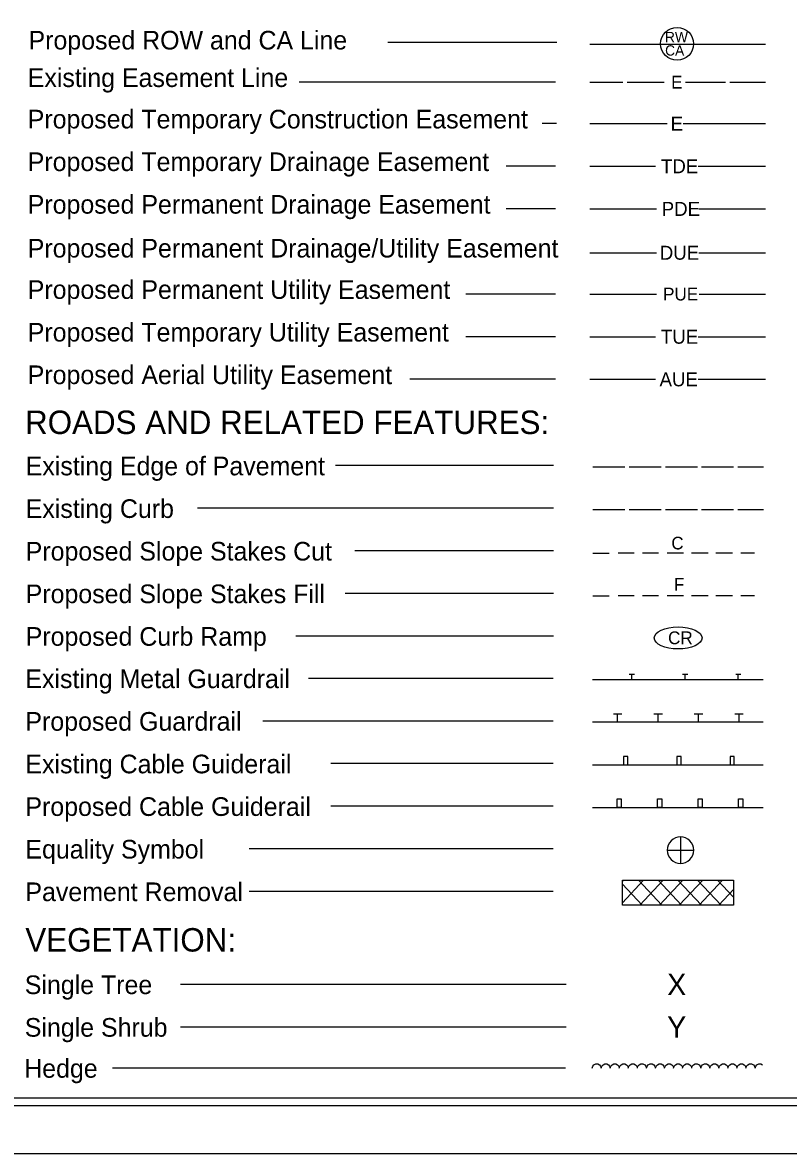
# Model space of a CAD drawing. Extents: x 1523758 to 1525442, y 311788 to 312888.
# Drawn here: x 1524321 to 1524680, y 311788 to 312319 of the extents above; entities that cross this region are included whole.
import ezdxf

# ---------------------------------------------------------------- set-up
doc = ezdxf.new("R2010")
doc.units = 0
for name, color, linetype in [('Prop Easement Permanent Drainage Utility', 7, 'Continuous'), ('Prop WCC CELL', 7, 'Continuous'), ('Sheet Cutting Line CELL', 7, 'Continuous'), ('Sheet Plot Border Inside CELL', 7, 'Continuous'), ('Sheet Plot Border Outside CELL', 7, 'Continuous'), ('Sheet Symbology CELL', 7, 'Continuous')]:
    doc.layers.add(name, color=color, linetype=linetype)

msp = doc.modelspace()

# ---------------------------------------------------------------- linework, layer by layer
at = {"layer": 'Prop Easement Permanent Drainage Utility'}
for p, q in [((1524586.95, 312211.16), (1524618.25, 312211.16)), ((1524638.25, 312211.16), (1524669.45, 312211.16))]:
    msp.add_line(p, q, dxfattribs=at)
at = {"layer": 'Prop WCC CELL'}
msp.add_ellipse((1524628.46, 312030.34), major_axis=(11.21, 0), ratio=0.462467, dxfattribs=at)
at = {"layer": 'Sheet Cutting Line CELL'}
msp.add_line((1523758.07, 311788.39), (1525442.07, 311788.39), dxfattribs=at)
msp.add_line((1523758.07, 311788.39), (1525442.07, 311788.39), dxfattribs=at)
at = {"layer": 'Sheet Plot Border Inside CELL'}
msp.add_lwpolyline([(1523771.07, 311810.84), (1525437.57, 311810.84), (1525437.57, 312865.94), (1523771.07, 312865.94)], close=True, dxfattribs=at)
at = {"layer": 'Sheet Plot Border Outside CELL'}
msp.add_lwpolyline([(1523758.07, 311788.39), (1525442.07, 311788.39), (1525442.07, 312888.39), (1523758.07, 312888.39)], close=True, dxfattribs=at)
at = {"layer": 'Sheet Symbology CELL'}
for p, q in [((1524571.56, 312309.81), (1524492.2, 312309.81)), ((1524586.96, 312309.04), (1524669.46, 312309.04)), ((1524570.92, 312291.2), (1524450.64, 312291.2)), ((1524586.95, 312291.2), (1524602.47, 312291.2)), ((1524604.47, 312291.2), (1524621.97, 312291.2)), ((1524631.97, 312291.2), (1524650.72, 312291.2)), ((1524652.72, 312291.2), (1524669.45, 312291.2)), ((1524571.31, 312271.74), (1524564.63, 312271.74)), ((1524586.95, 312271.74), (1524589.57, 312271.74)), ((1524589.57, 312271.74), (1524623.32, 312271.74)), ((1524630.82, 312271.74), (1524664.57, 312271.74)), ((1524664.57, 312271.74), (1524669.45, 312271.74)), ((1524570.92, 312251.74), (1524547.77, 312251.74)), ((1524586.95, 312251.74), (1524590.3, 312251.74)), ((1524590.3, 312251.74), (1524617.8, 312251.74)), ((1524637.8, 312251.74), (1524665.3, 312251.74)), ((1524665.3, 312251.74), (1524669.45, 312251.74)), ((1524570.92, 312231.74), (1524547.77, 312231.74)), ((1524586.95, 312231.74), (1524590.75, 312231.74)), ((1524590.75, 312231.74), (1524618.25, 312231.74)), ((1524638.25, 312231.74), (1524665.75, 312231.74)), ((1524665.75, 312231.74), (1524669.45, 312231.74)), ((1524570.92, 312191.73), (1524528.79, 312191.73)), ((1524586.95, 312191.73), (1524590.79, 312191.73)), ((1524590.79, 312191.73), (1524618.29, 312191.73)), ((1524638.29, 312191.73), (1524665.79, 312191.73)), ((1524665.79, 312191.73), (1524669.45, 312191.73)), ((1524570.92, 312171.73), (1524528.79, 312171.73)), ((1524586.95, 312171.73), (1524590.3, 312171.73)), ((1524590.3, 312171.73), (1524617.8, 312171.73)), ((1524637.8, 312171.73), (1524665.3, 312171.73)), ((1524665.3, 312171.73), (1524669.45, 312171.73)), ((1524570.92, 312151.73), (1524502.47, 312151.73)), ((1524586.95, 312151.73), (1524590.3, 312151.73)), ((1524590.3, 312151.73), (1524617.8, 312151.73)), ((1524637.8, 312151.73), (1524665.3, 312151.73)), ((1524665.3, 312151.73), (1524669.45, 312151.73)), ((1524569.96, 312111.21), (1524467.61, 312111.21)), ((1524588.49, 312110.63), (1524603.49, 312110.63)), ((1524605.49, 312110.63), (1524620.49, 312110.63)), ((1524622.49, 312110.63), (1524637.49, 312110.63)), ((1524639.49, 312110.63), (1524654.49, 312110.63)), ((1524656.49, 312110.63), (1524668.49, 312110.63)), ((1524569.96, 312091.21), (1524402.81, 312091.21)), ((1524588.49, 312090.63), (1524603.49, 312090.63)), ((1524605.49, 312090.63), (1524620.49, 312090.63)), ((1524622.49, 312090.63), (1524637.49, 312090.63)), ((1524639.49, 312090.63), (1524654.49, 312090.63)), ((1524656.49, 312090.63), (1524668.49, 312090.63)), ((1524569.96, 312071.21), (1524476.77, 312071.21)), ((1524588.49, 312070.16), (1524596.09, 312070.16)), ((1524607.79, 312070.16), (1524600.24, 312070.16)), ((1524619.29, 312070.16), (1524611.69, 312070.16)), ((1524631.04, 312070.16), (1524623.24, 312070.16)), ((1524642.49, 312070.16), (1524634.74, 312070.16)), ((1524654.04, 312070.16), (1524646.19, 312070.16)), ((1524664.34, 312070.16), (1524657.94, 312070.16)), ((1524569.96, 312051.21), (1524472.22, 312051.21)), ((1524588.49, 312050.16), (1524596.09, 312050.16)), ((1524607.79, 312050.16), (1524600.24, 312050.16)), ((1524619.29, 312050.16), (1524611.69, 312050.16)), ((1524631.04, 312050.16), (1524623.24, 312050.16)), ((1524642.49, 312050.16), (1524634.74, 312050.16)), ((1524654.04, 312050.16), (1524646.19, 312050.16)), ((1524664.34, 312050.16), (1524657.94, 312050.16)), ((1524569.96, 312031.21), (1524449.03, 312031.21)), ((1524569.8, 312011.33), (1524454.97, 312011.33)), ((1524588.33, 312010.75), (1524668.33, 312010.75)), ((1524605.47, 312013.25), (1524607.97, 312013.25)), ((1524606.72, 312010.75), (1524606.72, 312013.25)), ((1524630.47, 312013.25), (1524632.97, 312013.25)), ((1524631.72, 312010.75), (1524631.72, 312013.25)), ((1524655.47, 312013.25), (1524657.97, 312013.25)), ((1524656.72, 312010.75), (1524656.72, 312013.25)), ((1524598.06, 311994.7), (1524602.06, 311994.7)), ((1524600.06, 311990.75), (1524600.06, 311994.7)), ((1524617.06, 311994.7), (1524621.06, 311994.7)), ((1524619.06, 311990.75), (1524619.06, 311994.7)), ((1524636.06, 311994.7), (1524640.06, 311994.7)), ((1524638.06, 311990.75), (1524638.06, 311994.7)), ((1524655.06, 311994.7), (1524659.06, 311994.7)), ((1524657.06, 311990.75), (1524657.06, 311994.7)), ((1524569.8, 311991.33), (1524433.57, 311991.33)), ((1524668.33, 311990.75), (1524588.33, 311990.75)), ((1524569.8, 311971.33), (1524465.5, 311971.33)), ((1524588.33, 311970.75), (1524668.33, 311970.75)), ((1524569.8, 311951.33), (1524465.5, 311951.33)), ((1524588.33, 311950.75), (1524668.33, 311950.75)), ((1524629.56, 311936.99), (1524629.56, 311930.74)), ((1524569.8, 311931.33), (1524427.18, 311931.33)), ((1524623.31, 311930.74), (1524629.56, 311930.74)), ((1524629.56, 311930.74), (1524629.56, 311924.49)), ((1524629.56, 311930.74), (1524635.81, 311930.74)), ((1524602.28, 311916.61), (1524654.38, 311916.61)), ((1524602.28, 311904.91), (1524602.28, 311916.61)), ((1524602.28, 311916.01), (1524602.83, 311916.61)), ((1524602.28, 311906.06), (1524612.13, 311916.61)), ((1524611.53, 311904.91), (1524602.28, 311914.81)), ((1524620.83, 311904.91), (1524609.83, 311916.61)), ((1524610.43, 311904.91), (1524621.43, 311916.61)), ((1524630.08, 311904.91), (1524619.13, 311916.61)), ((1524619.68, 311904.91), (1524630.73, 311916.61)), ((1524639.38, 311904.91), (1524628.38, 311916.61)), ((1524628.98, 311904.91), (1524639.98, 311916.61)), ((1524648.68, 311904.91), (1524637.63, 311916.61)), ((1524638.28, 311904.91), (1524649.23, 311916.61)), ((1524654.38, 311908.66), (1524646.93, 311916.61)), ((1524654.38, 311916.61), (1524654.38, 311904.91)), ((1524569.8, 311911.33), (1524427.18, 311911.33)), ((1524647.53, 311904.91), (1524654.38, 311912.21)), ((1524654.38, 311904.91), (1524602.28, 311904.91)), ((1524575.94, 311867.68), (1524394.82, 311867.68)), ((1524575.94, 311847.68), (1524394.82, 311847.68)), ((1524575.67, 311828.42), (1524362.99, 311828.42)), ((1524588.07, 311828.42), (1524588.37, 311829.37)), ((1524588.37, 311829.37), (1524588.97, 311830.02)), ((1524588.97, 311830.02), (1524589.77, 311830.47)), ((1524589.77, 311830.47), (1524590.72, 311830.47)), ((1524590.72, 311830.47), (1524591.52, 311829.97)), ((1524591.52, 311829.97), (1524592.07, 311829.32)), ((1524592.07, 311829.32), (1524592.27, 311828.47)), ((1524592.32, 311828.42), (1524592.62, 311829.37)), ((1524592.62, 311829.37), (1524593.22, 311830.02)), ((1524593.22, 311830.02), (1524594.02, 311830.47)), ((1524594.02, 311830.47), (1524594.97, 311830.47)), ((1524594.97, 311830.47), (1524595.77, 311829.97)), ((1524595.77, 311829.97), (1524596.32, 311829.32)), ((1524596.32, 311829.32), (1524596.52, 311828.47)), ((1524596.57, 311828.42), (1524596.87, 311829.37)), ((1524596.87, 311829.37), (1524597.47, 311830.02)), ((1524597.47, 311830.02), (1524598.27, 311830.47)), ((1524598.27, 311830.47), (1524599.22, 311830.47)), ((1524599.22, 311830.47), (1524600.02, 311829.97)), ((1524600.02, 311829.97), (1524600.57, 311829.32)), ((1524600.57, 311829.32), (1524600.77, 311828.47)), ((1524600.82, 311828.42), (1524601.12, 311829.37)), ((1524601.12, 311829.37), (1524601.72, 311830.02)), ((1524601.72, 311830.02), (1524602.52, 311830.47)), ((1524602.52, 311830.47), (1524603.47, 311830.47)), ((1524603.47, 311830.47), (1524604.27, 311829.97)), ((1524604.27, 311829.97), (1524604.82, 311829.32)), ((1524604.82, 311829.32), (1524605.02, 311828.47)), ((1524605.07, 311828.42), (1524605.37, 311829.37)), ((1524605.37, 311829.37), (1524605.97, 311830.02)), ((1524605.97, 311830.02), (1524606.77, 311830.47)), ((1524606.77, 311830.47), (1524607.72, 311830.47)), ((1524607.72, 311830.47), (1524608.52, 311829.97)), ((1524608.52, 311829.97), (1524609.07, 311829.32)), ((1524609.07, 311829.32), (1524609.27, 311828.47)), ((1524609.32, 311828.42), (1524609.62, 311829.37)), ((1524609.62, 311829.37), (1524610.22, 311830.02)), ((1524610.22, 311830.02), (1524611.02, 311830.47)), ((1524611.02, 311830.47), (1524611.97, 311830.47)), ((1524611.97, 311830.47), (1524612.77, 311829.97)), ((1524612.77, 311829.97), (1524613.32, 311829.32)), ((1524613.32, 311829.32), (1524613.52, 311828.47)), ((1524613.57, 311828.42), (1524613.87, 311829.37)), ((1524613.87, 311829.37), (1524614.47, 311830.02)), ((1524614.47, 311830.02), (1524615.27, 311830.47)), ((1524615.27, 311830.47), (1524616.22, 311830.47)), ((1524616.22, 311830.47), (1524617.02, 311829.97)), ((1524617.02, 311829.97), (1524617.57, 311829.32)), ((1524617.57, 311829.32), (1524617.77, 311828.47)), ((1524617.82, 311828.42), (1524618.12, 311829.37)), ((1524618.12, 311829.37), (1524618.72, 311830.02)), ((1524618.72, 311830.02), (1524619.52, 311830.47)), ((1524619.52, 311830.47), (1524620.47, 311830.47)), ((1524620.47, 311830.47), (1524621.27, 311829.97)), ((1524621.27, 311829.97), (1524621.82, 311829.32)), ((1524621.82, 311829.32), (1524622.02, 311828.47)), ((1524622.07, 311828.42), (1524622.37, 311829.37)), ((1524622.37, 311829.37), (1524622.97, 311830.02)), ((1524622.97, 311830.02), (1524623.77, 311830.47)), ((1524623.77, 311830.47), (1524624.72, 311830.47)), ((1524624.72, 311830.47), (1524625.52, 311829.97)), ((1524625.52, 311829.97), (1524626.07, 311829.32)), ((1524626.07, 311829.32), (1524626.27, 311828.47)), ((1524626.32, 311828.42), (1524626.62, 311829.37)), ((1524626.62, 311829.37), (1524627.22, 311830.02)), ((1524627.22, 311830.02), (1524628.02, 311830.47)), ((1524628.02, 311830.47), (1524628.97, 311830.47)), ((1524628.97, 311830.47), (1524629.77, 311829.97)), ((1524629.77, 311829.97), (1524630.32, 311829.32)), ((1524630.32, 311829.32), (1524630.52, 311828.47)), ((1524630.57, 311828.42), (1524630.87, 311829.37)), ((1524630.87, 311829.37), (1524631.47, 311830.02)), ((1524631.47, 311830.02), (1524632.27, 311830.47)), ((1524632.27, 311830.47), (1524633.22, 311830.47)), ((1524633.22, 311830.47), (1524634.02, 311829.97)), ((1524634.02, 311829.97), (1524634.57, 311829.32)), ((1524634.57, 311829.32), (1524634.77, 311828.47)), ((1524634.82, 311828.42), (1524635.12, 311829.37)), ((1524635.12, 311829.37), (1524635.72, 311830.02)), ((1524635.72, 311830.02), (1524636.52, 311830.47)), ((1524636.52, 311830.47), (1524637.47, 311830.47)), ((1524637.47, 311830.47), (1524638.27, 311829.97)), ((1524638.27, 311829.97), (1524638.82, 311829.32)), ((1524638.82, 311829.32), (1524639.02, 311828.47)), ((1524639.07, 311828.42), (1524639.37, 311829.37)), ((1524639.37, 311829.37), (1524639.97, 311830.02)), ((1524639.97, 311830.02), (1524640.77, 311830.47)), ((1524640.77, 311830.47), (1524641.72, 311830.47)), ((1524641.72, 311830.47), (1524642.52, 311829.97)), ((1524642.52, 311829.97), (1524643.07, 311829.32)), ((1524643.07, 311829.32), (1524643.27, 311828.47)), ((1524643.32, 311828.42), (1524643.62, 311829.37)), ((1524643.62, 311829.37), (1524644.22, 311830.02)), ((1524644.22, 311830.02), (1524645.02, 311830.47)), ((1524645.02, 311830.47), (1524645.97, 311830.47)), ((1524645.97, 311830.47), (1524646.77, 311829.97)), ((1524646.77, 311829.97), (1524647.32, 311829.32)), ((1524647.32, 311829.32), (1524647.52, 311828.47)), ((1524647.57, 311828.42), (1524647.87, 311829.37)), ((1524647.87, 311829.37), (1524648.47, 311830.02)), ((1524648.47, 311830.02), (1524649.27, 311830.47)), ((1524649.27, 311830.47), (1524650.22, 311830.47)), ((1524650.22, 311830.47), (1524651.02, 311829.97)), ((1524651.02, 311829.97), (1524651.57, 311829.32)), ((1524651.57, 311829.32), (1524651.77, 311828.47)), ((1524651.82, 311828.42), (1524652.12, 311829.37)), ((1524652.12, 311829.37), (1524652.72, 311830.02)), ((1524652.72, 311830.02), (1524653.52, 311830.47)), ((1524653.52, 311830.47), (1524654.47, 311830.47)), ((1524654.47, 311830.47), (1524655.27, 311829.97)), ((1524655.27, 311829.97), (1524655.82, 311829.32)), ((1524655.82, 311829.32), (1524656.02, 311828.47)), ((1524656.07, 311828.42), (1524656.37, 311829.37)), ((1524656.37, 311829.37), (1524656.97, 311830.02)), ((1524656.97, 311830.02), (1524657.77, 311830.47)), ((1524657.77, 311830.47), (1524658.72, 311830.47)), ((1524658.72, 311830.47), (1524659.52, 311829.97)), ((1524659.52, 311829.97), (1524660.07, 311829.32)), ((1524660.07, 311829.32), (1524660.27, 311828.47)), ((1524660.32, 311828.42), (1524660.62, 311829.37)), ((1524660.62, 311829.37), (1524661.22, 311830.02)), ((1524661.22, 311830.02), (1524662.02, 311830.47)), ((1524662.02, 311830.47), (1524662.97, 311830.47)), ((1524662.97, 311830.47), (1524663.77, 311829.97)), ((1524663.77, 311829.97), (1524664.32, 311829.32)), ((1524664.32, 311829.32), (1524664.52, 311828.47)), ((1524664.57, 311828.42), (1524664.87, 311829.37)), ((1524664.87, 311829.37), (1524665.47, 311830.02)), ((1524665.47, 311830.02), (1524666.27, 311830.47)), ((1524666.27, 311830.47), (1524667.22, 311830.47)), ((1524667.22, 311830.47), (1524668.02, 311829.97)), ((1524668.02, 311829.97), (1524668.07, 311829.92))]:
    msp.add_line(p, q, dxfattribs=at)
for points in [[(1525425.07, 312863.39), (1523925.07, 312863.39), (1523925.07, 311814.41), (1525425.07, 311814.41)], [(1524602.81, 311970.75), (1524604.81, 311970.75), (1524604.81, 311974.75), (1524602.81, 311974.75)], [(1524627.81, 311970.75), (1524629.81, 311970.75), (1524629.81, 311974.75), (1524627.81, 311974.75)], [(1524652.81, 311970.75), (1524654.81, 311970.75), (1524654.81, 311974.75), (1524652.81, 311974.75)], [(1524599.8, 311954.75), (1524601.8, 311954.75), (1524601.8, 311950.75), (1524599.8, 311950.75)], [(1524618.8, 311954.75), (1524620.8, 311954.75), (1524620.8, 311950.75), (1524618.8, 311950.75)], [(1524637.8, 311954.75), (1524639.8, 311954.75), (1524639.8, 311950.75), (1524637.8, 311950.75)], [(1524656.8, 311954.75), (1524658.8, 311954.75), (1524658.8, 311950.75), (1524656.8, 311950.75)]]:
    msp.add_lwpolyline(points, close=True, dxfattribs=at)
msp.add_circle((1524627.95, 312309.19), 7.72, dxfattribs=at)
for start, end in [(89.9944, 179.9989), (359.9944, 89.9989), (179.9944, 269.9989), (269.9944, 359.9989)]:
    msp.add_arc((1524629.56, 311930.74), 6.25, start, end, dxfattribs=at)

# ---------------------------------------------------------------- texts
at = {"layer": 'Prop Easement Permanent Drainage Utility'}
msp.add_text('DUE', height=6.55, dxfattribs=at).set_placement((1524619.84, 312207.86))
at = {"layer": 'Prop WCC CELL'}
msp.add_text('CR', height=6, dxfattribs=at).set_placement((1524623.74, 312027.39))
at = {"layer": 'Sheet Symbology CELL'}
for s, height, p in [('Proposed ROW and CA Line', 8.75, (1524323.53, 312306.54)), ('RW', 4.838, (1524622.28, 312309.96)), ('CA', 4.838, (1524622.35, 312303.67)), ('Existing Easement Line', 8.75, (1524323.17, 312288.93)), ('E', 6, (1524625.17, 312288.2)), ('Proposed Temporary Construction Easement', 8.75, (1524323.17, 312269.48)), ('E', 6.55, (1524624.92, 312268.44)), ('Proposed Temporary Drainage Easement', 8.75, (1524323.17, 312249.48)), ('TDE', 6.55, (1524620.4, 312248.44)), ('Proposed Permanent Drainage Easement', 8.75, (1524323.17, 312229.48)), ('PDE', 6.55, (1524620.75, 312228.44)), ('Proposed Permanent Drainage/Utility Easement', 8.75, (1524323.17, 312208.9)), ('Proposed Permanent Utility Easement', 8.75, (1524323.17, 312189.47)), ('PUE', 6, (1524621.39, 312188.73)), ('Proposed Temporary Utility Easement', 8.75, (1524323.17, 312169.47)), ('TUE', 6.55, (1524620.38, 312168.43)), ('Proposed Aerial Utility Easement', 8.75, (1524323.17, 312149.47)), ('AUE', 6.55, (1524619.73, 312148.43)), ('ROADS AND RELATED FEATURES:', 11, (1524321.91, 312126.05)), ('Existing Edge of Pavement', 8.75, (1524322.21, 312106.66)), ('Existing Curb', 8.75, (1524322.21, 312086.66)), ('C', 5.93, (1524625.29, 312071.89)), ('Proposed Slope Stakes Cut', 8.75, (1524322.21, 312066.66)), ('Proposed Slope Stakes Fill', 8.75, (1524322.21, 312046.66)), ('F', 5.93, (1524626.49, 312052.52)), ('Proposed Curb Ramp', 8.75, (1524322.21, 312026.66)), ('Existing Metal Guardrail', 8.75, (1524322.05, 312006.78)), ('Proposed Guardrail', 8.75, (1524322.07, 311986.79)), ('Existing Cable Guiderail', 8.75, (1524322.07, 311966.79)), ('Proposed Cable Guiderail', 8.75, (1524322.07, 311946.79)), ('Equality Symbol', 8.75, (1524322.07, 311926.79)), ('Pavement Removal', 8.75, (1524322.07, 311906.79)), ('VEGETATION:', 11, (1524322.05, 311883.13)), ('Single Tree', 8.75, (1524321.78, 311863.16)), ('X', 10, (1524623.33, 311862.68)), ('Single Shrub', 8.75, (1524321.78, 311843.16)), ('Y', 10, (1524623.33, 311842.68)), ('Hedge', 8.75, (1524321.51, 311823.9))]:
    msp.add_text(s, height=height, dxfattribs=at).set_placement(p)

doc.saveas('drawing.dxf')
